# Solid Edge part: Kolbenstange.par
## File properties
Username: bmolnar
Dokumentum tartalom típus: 0
Author: bmolnar
Last saved by: bmolnar
Revision: 80
Sűrűség: 0,000 kg/m^3
Pontosság: 0,990
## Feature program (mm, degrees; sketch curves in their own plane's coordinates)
base feature "unnamed BaseFeature 1"
thread "unnamed Thread 1"
sketch for "Kihúzás_1" plane through (26.75, 0, 0) normal (1, 0, 0) x-axis (0, -1, 0)
  circle centre (0, 0) radius 31.5
extrude "Kihúzás_1" add finite 10.75 along +normal
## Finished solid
Body 1: solid body, 14 faces, 20 edges, 8 vertices.
  Faces by surface: plane 7, cylinder 4, cone 2, torus 1
  Edges by curve: circle 10, line 6, ellipse 2, intersection 2
Bounding box of the edges (mm; curved faces can reach further): 52.500 x 63.000 x 63.000, from (-15, -31.5, -31.5) to (37.5, 31.5, 31.5).
Cylindrical faces by radius (mm): R4.188 x2, R8 x1, R31.5 x1
Conical faces (half-angle, radius in mm at the cone's reference point): 45 deg R4.538 x1, 59 deg R2.094 x1
Toroidal faces (ring radius, tube radius in mm): R6.3 r1.7 x1
Planar faces by outward normal: +x 1, +z 1, -x 2, -z 1, oblique 2
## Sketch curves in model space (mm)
circle centre (26.75, 0, 0) radius 31.5
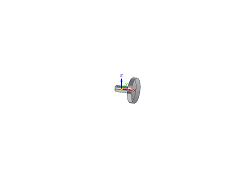
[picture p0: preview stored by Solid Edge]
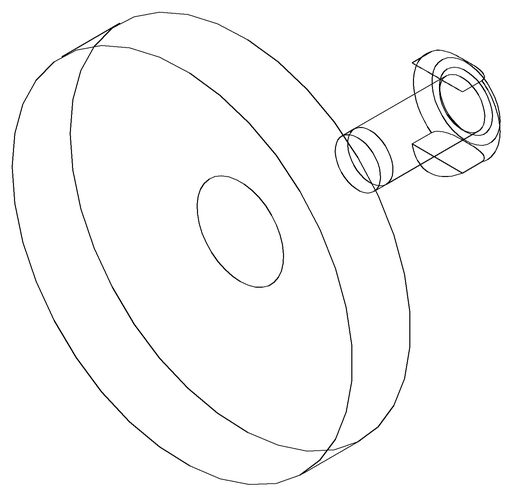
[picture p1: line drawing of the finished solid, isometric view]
